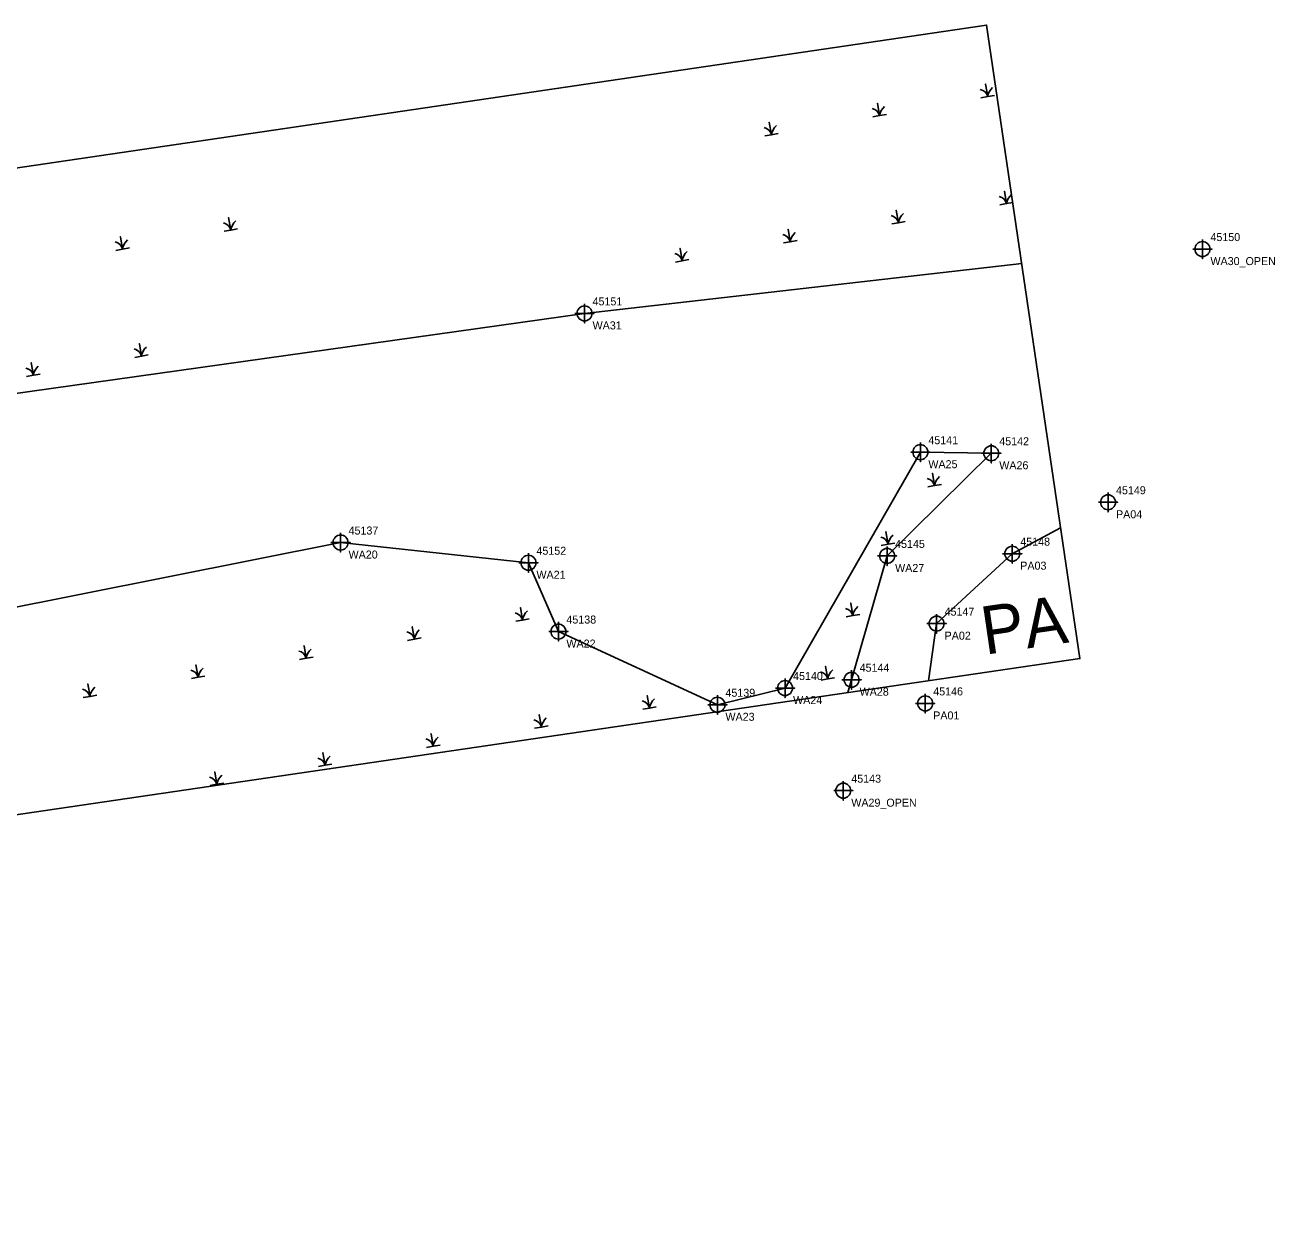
# Model space of a CAD drawing. Extents: x 2111078 to 2112659, y 581517 to 581899.
# Drawn here: x 2112268.6 to 2112659.1, y 581523.2 to 581899.2 of the extents above; entities that cross this region are included whole.
import ezdxf

# ---------------------------------------------------------------- set-up
doc = ezdxf.new("R2010")
doc.units = 0
for name, color, linetype in [('Default', 7, 'Continuous'), ('Exist Environmental Wetland Boundary', 7, 'Continuous'), ('Exist Environmental Wetland Boundary Cogo Comment', 7, 'Continuous'), ('Exist Environmental Wetland Boundary Cogo Number', 7, 'Continuous'), ('Exist Environmental Wetland Boundary Cogo Point CELL', 7, 'Continuous'), ('Exist Hydro Jurisdictional Stream or Body of Water Mitigable', 7, 'Continuous'), ('Exist Hydro Jurisdictional Stream or Body of Water Mitigable Cogo Comment', 7, 'Continuous'), ('Exist Hydro Jurisdictional Stream or Body of Water Mitigable Cogo Number', 7, 'Continuous'), ('Exist Hydro Jurisdictional Stream or Body of Water Mitigable Cogo Point CELL', 7, 'Continuous'), ('Exist Hydro Jurisdictional Stream or Body of Water Mitigable Text', 7, 'Continuous'), ('Exist Hydro Swamp or Marsh', 7, 'Continuous')]:
    doc.layers.add(name, color=color, linetype=linetype)

msp = doc.modelspace()

# ---------------------------------------------------------------- linework, layer by layer
at = {"layer": 'Default'}
msp.add_lwpolyline([(2111089.87, 581523.16), (2111077.52, 581722.78), (2111579.66, 581753.48), (2112568.99, 581899.18), (2112598.13, 581701.32), (2111600.4, 581554.74), (2111516.52, 581549.55)], close=True, dxfattribs=at)
at = {"layer": 'Exist Environmental Wetland Boundary'}
msp.add_lwpolyline([(2112579.95, 581824.73), (2112443.39, 581809.13), (2112256.64, 581782.86), (2112109, 581759.83), (2112096.72, 581743.78), (2112106.82, 581715.7), (2112118.04, 581694.33), (2112231.63, 581710.61), (2112367.17, 581737.55), (2112425.86, 581731.24), (2112435.22, 581709.75), (2112484.9, 581686.89), (2112506.03, 581692.11), (2112548.3, 581765.77), (2112570.44, 581765.42), (2112537.9, 581733.37), (2112525.65, 581690.67)], dxfattribs=at)
at = {"layer": 'Exist Environmental Wetland Boundary Cogo Point CELL'}
for points in [[(2112636.41, 581832.2), (2112636.41, 581826.2), (2112636.41, 581829.2), (2112639.41, 581829.2), (2112633.41, 581829.2)], [(2112443.39, 581812.12), (2112443.39, 581806.12), (2112443.39, 581809.12), (2112446.39, 581809.12), (2112440.39, 581809.12)], [(2112548.29, 581768.77), (2112548.29, 581762.77), (2112548.29, 581765.77), (2112551.29, 581765.77), (2112545.29, 581765.77)], [(2112570.44, 581768.42), (2112570.44, 581762.42), (2112570.44, 581765.42), (2112573.44, 581765.42), (2112567.44, 581765.42)], [(2112367.17, 581740.55), (2112367.17, 581734.55), (2112367.17, 581737.55), (2112370.17, 581737.55), (2112364.17, 581737.55)], [(2112537.9, 581736.36), (2112537.9, 581730.36), (2112537.9, 581733.36), (2112540.9, 581733.36), (2112534.9, 581733.36)], [(2112425.86, 581734.24), (2112425.86, 581728.24), (2112425.86, 581731.24), (2112428.86, 581731.24), (2112422.86, 581731.24)], [(2112435.22, 581712.75), (2112435.22, 581706.75), (2112435.22, 581709.75), (2112438.22, 581709.75), (2112432.22, 581709.75)], [(2112526.81, 581697.71), (2112526.81, 581691.71), (2112526.81, 581694.71), (2112529.81, 581694.71), (2112523.81, 581694.71)], [(2112506.03, 581695.11), (2112506.03, 581689.11), (2112506.03, 581692.11), (2112509.03, 581692.11), (2112503.03, 581692.11)], [(2112484.9, 581689.89), (2112484.9, 581683.89), (2112484.9, 581686.89), (2112487.9, 581686.89), (2112481.9, 581686.89)], [(2112524.21, 581663.06), (2112524.21, 581657.06), (2112524.21, 581660.06), (2112527.21, 581660.06), (2112521.21, 581660.06)]]:
    msp.add_lwpolyline(points, dxfattribs=at)
for centre in [(2112636.41, 581829.2), (2112443.39, 581809.12), (2112548.29, 581765.77), (2112570.44, 581765.42), (2112367.17, 581737.55), (2112537.9, 581733.36), (2112425.86, 581731.24), (2112435.22, 581709.75), (2112526.81, 581694.71), (2112506.03, 581692.11), (2112484.9, 581686.89), (2112524.21, 581660.06)]:
    msp.add_circle(centre, 2.34, dxfattribs=at)
at = {"layer": 'Exist Hydro Jurisdictional Stream or Body of Water Mitigable'}
msp.add_lwpolyline([(2112550.82, 581694.37), (2112553.36, 581712.22), (2112577, 581734.07), (2112592.11, 581742.18)], dxfattribs=at)
at = {"layer": 'Exist Hydro Jurisdictional Stream or Body of Water Mitigable Cogo Point CELL'}
for points in [[(2112606.91, 581753.13), (2112606.91, 581747.13), (2112606.91, 581750.13), (2112609.91, 581750.13), (2112603.91, 581750.13)], [(2112577, 581737.07), (2112577, 581731.07), (2112577, 581734.07), (2112580, 581734.07), (2112574, 581734.07)], [(2112553.36, 581715.22), (2112553.36, 581709.22), (2112553.36, 581712.22), (2112556.36, 581712.22), (2112550.36, 581712.22)], [(2112549.81, 581690.31), (2112549.81, 581684.31), (2112549.81, 581687.31), (2112552.81, 581687.31), (2112546.81, 581687.31)]]:
    msp.add_lwpolyline(points, dxfattribs=at)
for centre in [(2112606.91, 581750.13), (2112577, 581734.07), (2112553.36, 581712.22), (2112549.81, 581687.31)]:
    msp.add_circle(centre, 2.34, dxfattribs=at)
at = {"layer": 'Exist Hydro Swamp or Marsh'}
for p, q in [((2112552.43, 581757.08), (2112552.43, 581757.08)), ((2112537.9, 581738.78), (2112537.9, 581738.78)), ((2112526.92, 581716.49), (2112526.92, 581716.49)), ((2112519.08, 581696.72), (2112519.08, 581696.72))]:
    msp.add_line(p, q, dxfattribs=at)
for points in [[(2112567.22, 581876.46), (2112569.33, 581876.83), (2112568.65, 581880.72), (2112569.33, 581876.83), (2112571.45, 581877.21)], [(2112533.44, 581870.5), (2112535.56, 581870.88), (2112534.87, 581874.76), (2112535.56, 581870.88), (2112537.67, 581871.25)], [(2112499.66, 581864.55), (2112501.78, 581864.92), (2112501.09, 581868.81), (2112501.78, 581864.92), (2112503.89, 581865.29)], [(2112573.11, 581843.03), (2112575.23, 581843.4), (2112574.54, 581847.29), (2112575.23, 581843.4), (2112577.15, 581843.74)], [(2112539.33, 581837.07), (2112541.45, 581837.45), (2112540.76, 581841.33), (2112541.45, 581837.45), (2112543.57, 581837.82)], [(2112330.76, 581834.77), (2112332.88, 581835.14), (2112332.19, 581839.03), (2112332.88, 581835.14), (2112334.99, 581835.51)], [(2112296.98, 581828.81), (2112299.1, 581829.18), (2112298.41, 581833.07), (2112299.1, 581829.18), (2112301.21, 581829.56)], [(2112505.55, 581831.12), (2112507.67, 581831.49), (2112506.98, 581835.38), (2112507.67, 581831.49), (2112509.79, 581831.87)], [(2112471.77, 581825.16), (2112473.89, 581825.54), (2112473.21, 581829.42), (2112473.89, 581825.54), (2112476.01, 581825.91)], [(2112302.87, 581795.38), (2112304.99, 581795.75), (2112304.31, 581799.64), (2112304.99, 581795.75), (2112307.11, 581796.13)], [(2112269.09, 581789.42), (2112271.21, 581789.8), (2112270.53, 581793.68), (2112271.21, 581789.8), (2112273.33, 581790.17)], [(2112550.62, 581754.95), (2112552.74, 581755.32), (2112552.05, 581759.21), (2112552.74, 581755.32), (2112554.85, 581755.7)], [(2112536.09, 581736.65), (2112538.21, 581737.03), (2112537.53, 581740.91), (2112538.21, 581737.03), (2112540.33, 581737.4)], [(2112421.9, 581712.96), (2112424.01, 581713.33), (2112423.33, 581717.22), (2112424.01, 581713.33), (2112426.13, 581713.71)], [(2112525.11, 581714.37), (2112527.23, 581714.74), (2112526.55, 581718.62), (2112527.23, 581714.74), (2112529.35, 581715.11)], [(2112388.12, 581707), (2112390.23, 581707.38), (2112389.55, 581711.26), (2112390.23, 581707.38), (2112392.35, 581707.75)], [(2112354.34, 581701.05), (2112356.45, 581701.42), (2112355.77, 581705.31), (2112356.45, 581701.42), (2112358.57, 581701.8)], [(2112320.56, 581695.09), (2112322.68, 581695.47), (2112321.99, 581699.35), (2112322.68, 581695.47), (2112324.79, 581695.84)], [(2112517.27, 581694.59), (2112519.39, 581694.96), (2112518.7, 581698.85), (2112519.39, 581694.96), (2112521.5, 581695.34)], [(2112286.78, 581689.14), (2112288.9, 581689.51), (2112288.21, 581693.39), (2112288.9, 581689.51), (2112291.01, 581689.88)], [(2112461.57, 581685.49), (2112463.69, 581685.86), (2112463, 581689.75), (2112463.69, 581685.86), (2112465.81, 581686.23)], [(2112427.79, 581679.53), (2112429.91, 581679.91), (2112429.22, 581683.79), (2112429.91, 581679.91), (2112432.03, 581680.28)], [(2112394.01, 581673.58), (2112396.13, 581673.95), (2112395.44, 581677.83), (2112396.13, 581673.95), (2112398.25, 581674.32)], [(2112360.23, 581667.62), (2112362.35, 581667.99), (2112361.66, 581671.88), (2112362.35, 581667.99), (2112364.47, 581668.37)], [(2112326.45, 581661.66), (2112328.57, 581662.04), (2112327.88, 581665.92), (2112328.57, 581662.04), (2112330.69, 581662.41)]]:
    msp.add_lwpolyline(points, dxfattribs=at)
for centre, radius, start, end in [((2112566.35, 581876.08), 3.07, 14.1403, 77.535), ((2112574.09, 581876.13), 4.81, 132.1274, 171.6222), ((2112532.57, 581870.13), 3.07, 14.1403, 77.535), ((2112540.31, 581870.18), 4.81, 132.1274, 171.6222), ((2112506.53, 581864.22), 4.81, 132.1274, 171.6222), ((2112498.79, 581864.17), 3.07, 14.1403, 77.535), ((2112572.25, 581842.65), 3.07, 14.1403, 77.535), ((2112579.98, 581842.7), 4.81, 132.1274, 171.6222), ((2112546.2, 581836.75), 4.81, 132.1274, 171.6222), ((2112329.9, 581834.39), 3.07, 14.1403, 77.535), ((2112337.63, 581834.44), 4.81, 132.1274, 171.6222), ((2112538.47, 581836.7), 3.07, 14.1403, 77.535), ((2112303.85, 581828.48), 4.81, 132.1274, 171.6222), ((2112504.69, 581830.74), 3.07, 14.1403, 77.535), ((2112512.42, 581830.79), 4.81, 132.1274, 171.6222), ((2112296.12, 581828.43), 3.07, 14.1403, 77.535), ((2112478.64, 581824.84), 4.81, 132.1274, 171.6222), ((2112470.91, 581824.78), 3.07, 14.1403, 77.535), ((2112302.01, 581795), 3.07, 14.1403, 77.535), ((2112309.75, 581795.05), 4.81, 132.1274, 171.6222), ((2112268.23, 581789.05), 3.07, 14.1403, 77.535), ((2112275.97, 581789.1), 4.81, 132.1274, 171.6222), ((2112557.49, 581754.62), 4.81, 132.1274, 171.6222), ((2112549.75, 581754.57), 3.07, 14.1403, 77.535), ((2112535.23, 581736.28), 3.07, 14.1403, 77.535), ((2112542.97, 581736.33), 4.81, 132.1274, 171.6222), ((2112421.03, 581712.58), 3.07, 14.1403, 77.535), ((2112428.77, 581712.63), 4.81, 132.1274, 171.6222), ((2112524.25, 581713.99), 3.07, 14.1403, 77.535), ((2112531.98, 581714.04), 4.81, 132.1274, 171.6222), ((2112387.25, 581706.63), 3.07, 14.1403, 77.535), ((2112394.99, 581706.68), 4.81, 132.1274, 171.6222), ((2112353.47, 581700.67), 3.07, 14.1403, 77.535), ((2112361.21, 581700.72), 4.81, 132.1274, 171.6222), ((2112319.69, 581694.71), 3.07, 14.1403, 77.535), ((2112327.43, 581694.77), 4.81, 132.1274, 171.6222), ((2112516.4, 581694.21), 3.07, 14.1403, 77.535), ((2112524.14, 581694.26), 4.81, 132.1274, 171.6222), ((2112285.91, 581688.76), 3.07, 14.1403, 77.535), ((2112293.65, 581688.81), 4.81, 132.1274, 171.6222), ((2112460.71, 581685.11), 3.07, 14.1403, 77.535), ((2112468.44, 581685.16), 4.81, 132.1274, 171.6222), ((2112426.93, 581679.15), 3.07, 14.1403, 77.535), ((2112434.66, 581679.21), 4.81, 132.1274, 171.6222), ((2112393.15, 581673.2), 3.07, 14.1403, 77.535), ((2112400.88, 581673.25), 4.81, 132.1274, 171.6222), ((2112359.37, 581667.24), 3.07, 14.1403, 77.535), ((2112367.1, 581667.29), 4.81, 132.1274, 171.6222), ((2112325.59, 581661.29), 3.07, 14.1403, 77.535), ((2112333.32, 581661.34), 4.81, 132.1274, 171.6222)]:
    msp.add_arc(centre, radius, start, end, dxfattribs=at)

# ---------------------------------------------------------------- texts
at = {"layer": 'Exist Environmental Wetland Boundary Cogo Comment'}
for s, p in [('WA30_OPEN', (2112638.91, 581824.2)), ('WA31', (2112445.89, 581804.12)), ('WA25', (2112550.79, 581760.77)), ('WA26', (2112572.94, 581760.43)), ('WA20', (2112369.67, 581732.55)), ('WA27', (2112540.4, 581728.36)), ('WA21', (2112428.36, 581726.24)), ('WA22', (2112437.72, 581704.75)), ('WA28', (2112529.31, 581689.71)), ('WA24', (2112508.53, 581687.11)), ('WA23', (2112487.4, 581681.89)), ('WA29_OPEN', (2112526.71, 581655.06))]:
    msp.add_text(s, height=2.5, dxfattribs=at).set_placement(p)
at = {"layer": 'Exist Environmental Wetland Boundary Cogo Number'}
for s, p in [('45150', (2112638.91, 581831.7)), ('45151', (2112445.89, 581811.62)), ('45141', (2112550.79, 581768.27)), ('45142', (2112572.94, 581767.93)), ('45137', (2112369.67, 581740.05)), ('45145', (2112540.4, 581735.86)), ('45152', (2112428.36, 581733.74)), ('45138', (2112437.72, 581712.25)), ('45144', (2112529.31, 581697.21)), ('45140', (2112508.53, 581694.61)), ('45139', (2112487.4, 581689.39)), ('45143', (2112526.71, 581662.56))]:
    msp.add_text(s, height=2.5, dxfattribs=at).set_placement(p)
at = {"layer": 'Exist Hydro Jurisdictional Stream or Body of Water Mitigable Cogo Comment'}
for s, p in [('PA04', (2112609.41, 581745.13)), ('PA03', (2112579.5, 581729.07)), ('PA02', (2112555.86, 581707.22)), ('PA01', (2112552.31, 581682.31))]:
    msp.add_text(s, height=2.5, dxfattribs=at).set_placement(p)
at = {"layer": 'Exist Hydro Jurisdictional Stream or Body of Water Mitigable Cogo Number'}
for s, p in [('45149', (2112609.41, 581752.63)), ('45148', (2112579.5, 581736.57)), ('45147', (2112555.86, 581714.72)), ('45146', (2112552.31, 581689.81))]:
    msp.add_text(s, height=2.5, dxfattribs=at).set_placement(p)
at = {"layer": 'Exist Hydro Jurisdictional Stream or Body of Water Mitigable Text'}
msp.add_text('PA', height=15, rotation=8.3579, dxfattribs=at).set_placement((2112568.47, 581702.49))

doc.saveas('drawing.dxf')
